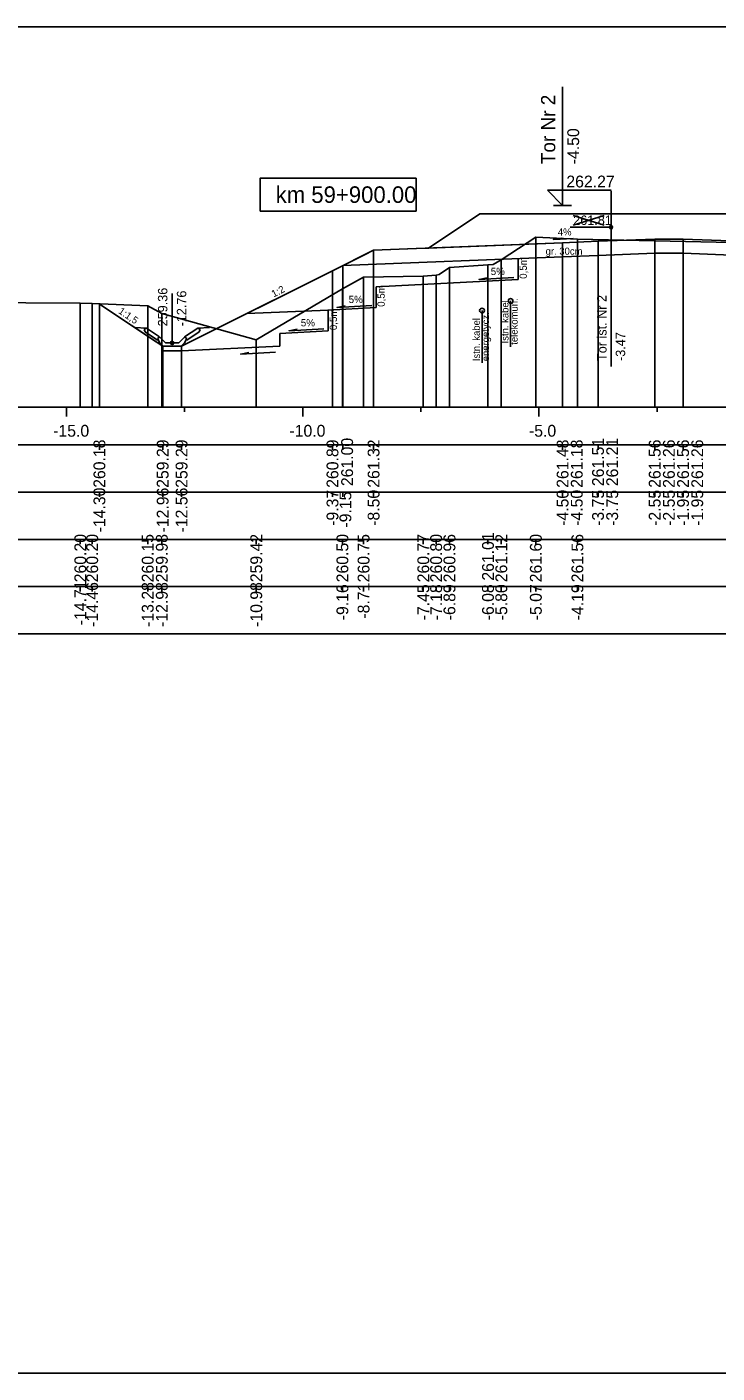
# Model space of a CAD drawing. Extents: x 6516023 to 6560129, y 5513077 to 5529206.
# Drawn here: x 6517839.38 to 6517853.98, y 5514451.16 to 5514479.66 of the extents above; entities that cross this region are included whole.
import ezdxf

# ---------------------------------------------------------------- set-up
doc = ezdxf.new("R2010")
doc.units = 0
for name, color, linetype in [('IR_default', 7, 'Continuous'), ('TOR_PRZEK_P-kable', 7, 'Continuous'), ('TOR_PRZEK_P-komponent', 7, 'Continuous'), ('TOR_PRZEK_P-odwodnienie', 7, 'Continuous'), ('TOR_PRZEK_P-opisy', 7, 'Continuous'), ('TOR_PRZEK_P-schodkowanie+wymiana', 7, 'Continuous'), ('TOR_PRZEK_P-tabelka istniejace', 7, 'Continuous'), ('TOR_PRZEK_P-tabelka projektowane', 7, 'Continuous'), ('TOR_PRZEK_P-teren istniejacy', 7, 'Continuous'), ('TOR_PRZEK_P-tory istniejace', 7, 'Continuous'), ('TOR_PRZEK_P-tory projektowane', 7, 'Continuous'), ('TOR_PRZEK_P-uklad odniesienia', 7, 'Continuous'), ('TOR_PRZEK_P-warstwa ochronna I', 7, 'Continuous'), ('TOR_PRZEK_P-warstwa ochronna II', 7, 'Continuous'), ('TOR_PS_T-skarpy projektowane', 7, 'Continuous'), ('TOR_RAMKI-ramka+tabelka 1', 7, 'Continuous')]:
    doc.layers.add(name, color=color, linetype=linetype)

msp = doc.modelspace()

# ---------------------------------------------------------------- linework, layer by layer
at = {"layer": 'IR_default'}
msp.add_lwpolyline([(6517840.91, 5514473.789), (6517841.969, 5514473.083), (6517842.249, 5514472.896), (6517842.339, 5514472.896), (6517842.649, 5514472.896), (6517843.365, 5514473.254), (6517845.843, 5514474.493), (6517845.843, 5514474.493), (6517845.843, 5514474.493), (6517846.518, 5514474.831), (6517846.713, 5514474.928), (6517847.617, 5514474.964), (6517847.878, 5514474.975), (6517848.72, 5514475.536), (6517848.963, 5514475.698), (6517851.679, 5514475.698), (6517852.463, 5514475.698), (6517853.239, 5514475.698), (6517853.463, 5514475.698), (6517856.179, 5514475.698)], dxfattribs=at)
at = {"layer": 'TOR_PRZEK_P-kable'}
for p, q in [((6517849.613, 5514473.854), (6517849.613, 5514472.88)), ((6517849.008, 5514473.651), (6517849.008, 5514472.542))]:
    msp.add_line(p, q, dxfattribs=at)
for centre in [(6517849.613, 5514473.854), (6517849.008, 5514473.651)]:
    msp.add_circle(centre, 0.05, dxfattribs=at)
at = {"layer": 'TOR_PRZEK_P-komponent'}
msp.add_lwpolyline([(6517848.963, 5514475.698), (6517852.463, 5514475.698), (6517853.463, 5514475.698), (6517856.963, 5514475.698), (6517857.513, 5514475.699), (6517861.013, 5514475.699), (6517862.358, 5514474.802), (6517858.513, 5514474.956), (6517855.213, 5514475.088), (6517854.463, 5514475.118), (6517853.263, 5514475.166), (6517852.663, 5514475.166), (6517851.463, 5514475.118), (6517850.713, 5514475.088), (6517847.878, 5514474.975)], close=True, dxfattribs=at)
at = {"layer": 'TOR_PRZEK_P-odwodnienie'}
for p, q in [((6517842.449, 5514472.966), (6517842.449, 5514474.01)), ((6517842.185, 5514473.092), (6517841.904, 5514473.279)), ((6517842.714, 5514473.092), (6517842.994, 5514473.279)), ((6517842.14, 5514473.025), (6517841.879, 5514473.2)), ((6517842.151, 5514473.042), (6517842.14, 5514473.025)), ((6517842.142, 5514473.061), (6517842.189, 5514473.085)), ((6517842.185, 5514473.092), (6517842.176, 5514473.079)), ((6517842.309, 5514472.966), (6517842.189, 5514473.085)), ((6517842.589, 5514472.966), (6517842.709, 5514473.085)), ((6517842.709, 5514473.085), (6517842.757, 5514473.061)), ((6517842.714, 5514473.092), (6517842.722, 5514473.079)), ((6517842.747, 5514473.042), (6517842.758, 5514473.025)), ((6517842.758, 5514473.025), (6517843.02, 5514473.2)), ((6517842.259, 5514472.896), (6517842.639, 5514472.896)), ((6517842.309, 5514472.966), (6517842.589, 5514472.966))]:
    msp.add_line(p, q, dxfattribs=at)
for points in [[(6517841.658, 5514473.291), (6517841.904, 5514473.279)], [(6517841.854, 5514473.252), (6517841.904, 5514473.279)], [(6517843.241, 5514473.291), (6517842.994, 5514473.279)], [(6517843.044, 5514473.252), (6517842.994, 5514473.279)], [(6517841.854, 5514473.252), (6517841.879, 5514473.2)], [(6517842.176, 5514473.079), (6517842.141, 5514473.061)], [(6517842.141, 5514473.061), (6517842.151, 5514473.042)], [(6517842.189, 5514472.966), (6517842.142, 5514473.061)], [(6517842.709, 5514472.966), (6517842.757, 5514473.061)], [(6517842.722, 5514473.079), (6517842.757, 5514473.061)], [(6517842.757, 5514473.061), (6517842.747, 5514473.042)], [(6517843.044, 5514473.252), (6517843.02, 5514473.2)], [(6517842.259, 5514472.896), (6517842.189, 5514472.966)], [(6517842.249, 5514472.896), (6517842.248, 5514472.897), (6517842.249, 5514472.896), (6517842.248, 5514472.896), (6517842.249, 5514472.896), (6517842.249, 5514472.896), (6517842.249, 5514472.896), (6517842.249, 5514472.897)], [(6517842.249, 5514472.896), (6517842.249, 5514472.896), (6517842.249, 5514472.896), (6517842.249, 5514472.895), (6517842.249, 5514472.896), (6517842.25, 5514472.895), (6517842.249, 5514472.896), (6517842.25, 5514472.896)], [(6517842.649, 5514472.896), (6517842.249, 5514472.896), (6517842.249, 5514472.796), (6517842.649, 5514472.796), (6517842.649, 5514472.896)], [(6517842.639, 5514472.896), (6517842.709, 5514472.966)], [(6517842.649, 5514472.896), (6517842.648, 5514472.897), (6517842.649, 5514472.896), (6517842.648, 5514472.896), (6517842.649, 5514472.896), (6517842.649, 5514472.896), (6517842.649, 5514472.896), (6517842.649, 5514472.897)], [(6517842.649, 5514472.896), (6517842.649, 5514472.896), (6517842.649, 5514472.896), (6517842.649, 5514472.895), (6517842.649, 5514472.896), (6517842.65, 5514472.895), (6517842.649, 5514472.896), (6517842.65, 5514472.896)]]:
    msp.add_lwpolyline(points, dxfattribs=at)
msp.add_circle((6517842.449, 5514472.966), 0.035, dxfattribs=at)
at = {"layer": 'TOR_PRZEK_P-opisy'}
msp.add_lwpolyline([(6517850.936, 5514475.175), (6517850.518, 5514475.156), (6517850.686, 5514475.184)], dxfattribs=at)
at = {"layer": 'TOR_PRZEK_P-schodkowanie+wymiana'}
for p, q in [((6517849.775, 5514474.751), (6517849.775, 5514474.307)), ((6517849.775, 5514474.307), (6517846.767, 5514474.157)), ((6517846.767, 5514474.157), (6517846.767, 5514473.714)), ((6517845.755, 5514473.663), (6517844.033, 5514473.588)), ((6517846.767, 5514473.714), (6517845.744, 5514473.663)), ((6517845.755, 5514473.663), (6517845.755, 5514473.22)), ((6517845.755, 5514473.22), (6517844.732, 5514473.169)), ((6517844.732, 5514473.169), (6517844.732, 5514472.9)), ((6517844.732, 5514472.9), (6517842.649, 5514472.796))]:
    msp.add_line(p, q, dxfattribs=at)
at = {"layer": 'TOR_PRZEK_P-tabelka istniejace'}
for p, q in [((6517840.506, 5514468.706), (6517840.506, 5514468.806)), ((6517840.757, 5514468.706), (6517840.757, 5514468.806)), ((6517841.932, 5514468.706), (6517841.932, 5514468.806)), ((6517842.231, 5514468.706), (6517842.231, 5514468.806)), ((6517844.23, 5514468.706), (6517844.23, 5514468.806)), ((6517846.053, 5514468.706), (6517846.053, 5514468.806)), ((6517846.501, 5514468.706), (6517846.501, 5514468.806)), ((6517847.765, 5514468.706), (6517847.765, 5514468.806)), ((6517848.037, 5514468.706), (6517848.037, 5514468.806)), ((6517848.319, 5514468.706), (6517848.319, 5514468.806)), ((6517849.134, 5514468.706), (6517849.134, 5514468.806)), ((6517849.416, 5514468.706), (6517849.416, 5514468.806)), ((6517850.147, 5514468.706), (6517850.147, 5514468.806)), ((6517851.027, 5514468.706), (6517851.027, 5514468.806)), ((6517814.163, 5514467.806), (6517897.963, 5514467.806)), ((6517840.506, 5514467.706), (6517840.506, 5514467.806)), ((6517840.757, 5514467.706), (6517840.757, 5514467.806)), ((6517841.932, 5514467.706), (6517841.932, 5514467.806)), ((6517842.231, 5514467.706), (6517842.231, 5514467.806)), ((6517844.23, 5514467.706), (6517844.23, 5514467.806)), ((6517846.053, 5514467.706), (6517846.053, 5514467.806)), ((6517846.501, 5514467.706), (6517846.501, 5514467.806)), ((6517847.765, 5514467.706), (6517847.765, 5514467.806)), ((6517848.037, 5514467.706), (6517848.037, 5514467.806)), ((6517848.319, 5514467.706), (6517848.319, 5514467.806)), ((6517849.134, 5514467.706), (6517849.134, 5514467.806)), ((6517849.416, 5514467.706), (6517849.416, 5514467.806)), ((6517850.147, 5514467.706), (6517850.147, 5514467.806)), ((6517851.027, 5514467.706), (6517851.027, 5514467.806))]:
    msp.add_line(p, q, dxfattribs=at)
for points in [[(6517850.147, 5514475.204), (6517850.147, 5514471.806), (6517850.147, 5514471.676), (6517850.147, 5514471.606)], [(6517851.027, 5514475.162), (6517851.027, 5514471.806), (6517851.027, 5514471.676), (6517851.027, 5514471.606)], [(6517849.416, 5514474.725), (6517849.416, 5514471.806), (6517849.416, 5514471.676), (6517849.416, 5514471.606)], [(6517848.319, 5514474.561), (6517848.319, 5514471.806), (6517848.319, 5514471.676), (6517848.319, 5514471.606)], [(6517849.134, 5514474.616), (6517849.134, 5514471.806), (6517849.134, 5514471.676), (6517849.134, 5514471.606)], [(6517846.501, 5514474.355), (6517846.501, 5514471.806), (6517846.501, 5514471.676), (6517846.501, 5514471.606)], [(6517847.765, 5514474.378), (6517847.765, 5514471.806), (6517847.765, 5514471.676), (6517847.765, 5514471.606)], [(6517848.037, 5514474.402), (6517848.037, 5514471.806), (6517848.037, 5514471.676), (6517848.037, 5514471.606)], [(6517846.053, 5514474.11), (6517846.053, 5514471.806), (6517846.053, 5514471.676), (6517846.053, 5514471.606)], [(6517840.506, 5514473.811), (6517840.506, 5514471.806), (6517840.506, 5514471.676), (6517840.506, 5514471.606)], [(6517840.757, 5514473.803), (6517840.757, 5514471.806), (6517840.757, 5514471.676), (6517840.757, 5514471.606)], [(6517841.932, 5514473.751), (6517841.932, 5514471.806), (6517841.932, 5514471.676), (6517841.932, 5514471.606)], [(6517842.231, 5514473.59), (6517842.231, 5514471.806), (6517842.231, 5514471.676), (6517842.231, 5514471.606)], [(6517844.23, 5514473.028), (6517844.23, 5514471.806), (6517844.23, 5514471.676), (6517844.23, 5514471.606)]]:
    msp.add_lwpolyline(points, dxfattribs=at)
msp.add_lwpolyline([(6517814.163, 5514468.806), (6517814.163, 5514466.806), (6517897.963, 5514466.806), (6517897.963, 5514468.806)], close=True, dxfattribs=at)
at = {"layer": 'TOR_PRZEK_P-tabelka projektowane'}
for p, q in [((6517840.91, 5514470.706), (6517840.91, 5514470.806)), ((6517842.249, 5514470.706), (6517842.249, 5514470.806)), ((6517842.649, 5514470.706), (6517842.649, 5514470.806)), ((6517845.843, 5514470.706), (6517845.843, 5514470.806)), ((6517846.061, 5514470.706), (6517846.061, 5514470.806)), ((6517846.713, 5514470.706), (6517846.713, 5514470.806)), ((6517850.713, 5514470.706), (6517850.713, 5514470.806)), ((6517850.713, 5514470.706), (6517850.713, 5514470.806)), ((6517851.463, 5514470.706), (6517851.463, 5514470.806)), ((6517851.463, 5514470.706), (6517851.463, 5514470.806)), ((6517852.663, 5514470.706), (6517852.663, 5514470.806)), ((6517852.663, 5514470.706), (6517852.663, 5514470.806)), ((6517853.263, 5514470.706), (6517853.263, 5514470.806)), ((6517853.263, 5514470.706), (6517853.263, 5514470.806)), ((6517814.163, 5514469.806), (6517897.963, 5514469.806)), ((6517840.91, 5514469.706), (6517840.91, 5514469.806)), ((6517842.249, 5514469.706), (6517842.249, 5514469.806)), ((6517842.649, 5514469.706), (6517842.649, 5514469.806)), ((6517845.843, 5514469.706), (6517845.843, 5514469.806)), ((6517846.061, 5514469.706), (6517846.061, 5514469.806)), ((6517846.713, 5514469.706), (6517846.713, 5514469.806)), ((6517850.713, 5514469.706), (6517850.713, 5514469.806)), ((6517850.713, 5514469.706), (6517850.713, 5514469.806)), ((6517851.463, 5514469.706), (6517851.463, 5514469.806)), ((6517851.463, 5514469.706), (6517851.463, 5514469.806)), ((6517852.663, 5514469.706), (6517852.663, 5514469.806)), ((6517852.663, 5514469.706), (6517852.663, 5514469.806)), ((6517853.263, 5514469.706), (6517853.263, 5514469.806)), ((6517853.263, 5514469.706), (6517853.263, 5514469.806))]:
    msp.add_line(p, q, dxfattribs=at)
for points in [[(6517850.713, 5514475.088), (6517850.713, 5514471.806), (6517850.713, 5514471.676), (6517850.713, 5514471.606)], [(6517851.463, 5514475.118), (6517851.463, 5514471.806), (6517851.463, 5514471.676), (6517851.463, 5514471.606)], [(6517852.663, 5514475.166), (6517852.663, 5514471.806), (6517852.663, 5514471.676), (6517852.663, 5514471.606)], [(6517853.263, 5514475.166), (6517853.263, 5514471.806), (6517853.263, 5514471.676), (6517853.263, 5514471.606)], [(6517846.713, 5514474.928), (6517846.713, 5514471.806), (6517846.713, 5514471.676), (6517846.713, 5514471.606)], [(6517850.713, 5514474.788), (6517850.713, 5514471.806), (6517850.713, 5514471.676), (6517850.713, 5514471.606)], [(6517851.463, 5514474.818), (6517851.463, 5514471.806), (6517851.463, 5514471.676), (6517851.463, 5514471.606)], [(6517852.663, 5514474.866), (6517852.663, 5514471.806), (6517852.663, 5514471.676), (6517852.663, 5514471.606)], [(6517853.263, 5514474.866), (6517853.263, 5514471.806), (6517853.263, 5514471.676), (6517853.263, 5514471.606)], [(6517845.843, 5514474.493), (6517845.843, 5514471.806), (6517845.843, 5514471.676), (6517845.843, 5514471.606)], [(6517846.061, 5514474.602), (6517846.061, 5514471.806), (6517846.061, 5514471.676), (6517846.061, 5514471.606)], [(6517840.91, 5514473.789), (6517840.91, 5514471.806), (6517840.91, 5514471.676), (6517840.91, 5514471.606)], [(6517842.249, 5514472.896), (6517842.249, 5514471.806), (6517842.249, 5514471.676), (6517842.249, 5514471.606)], [(6517842.649, 5514472.896), (6517842.649, 5514471.806), (6517842.649, 5514471.676), (6517842.649, 5514471.606)]]:
    msp.add_lwpolyline(points, dxfattribs=at)
msp.add_lwpolyline([(6517814.163, 5514470.806), (6517814.163, 5514468.806), (6517897.963, 5514468.806), (6517897.963, 5514470.806)], close=True, dxfattribs=at)
at = {"layer": 'TOR_PRZEK_P-teren istniejacy'}
msp.add_lwpolyline([(6517837.044, 5514473.827), (6517840.506, 5514473.811), (6517840.757, 5514473.803), (6517841.932, 5514473.751), (6517842.231, 5514473.59), (6517844.23, 5514473.028), (6517846.053, 5514474.11), (6517846.501, 5514474.355), (6517847.765, 5514474.378), (6517848.037, 5514474.402), (6517848.103, 5514474.417), (6517848.319, 5514474.561), (6517849.134, 5514474.616), (6517849.246, 5514474.627), (6517849.416, 5514474.725), (6517850.147, 5514475.204), (6517851.027, 5514475.162), (6517859.84, 5514474.971)], dxfattribs=at)
at = {"layer": 'TOR_PRZEK_P-tory istniejace'}
for p, q in [((6517851.738, 5514476.189), (6517851.738, 5514472.469)), ((6517850.938, 5514475.461), (6517851.59, 5514475.664)), ((6517850.938, 5514475.664), (6517851.59, 5514475.461)), ((6517851.738, 5514475.414), (6517850.872, 5514475.414))]:
    msp.add_line(p, q, dxfattribs=at)
msp.add_circle((6517851.738, 5514475.414), 0.035, dxfattribs=at)
at = {"layer": 'TOR_PRZEK_P-tory projektowane'}
for p, q in [((6517850.713, 5514476.756), (6517850.713, 5514478.388)), ((6517850.713, 5514476.756), (6517850.713, 5514475.878)), ((6517850.713, 5514475.878), (6517850.394, 5514476.197)), ((6517850.394, 5514476.197), (6517851.738, 5514476.197)), ((6517850.521, 5514475.878), (6517850.905, 5514475.878))]:
    msp.add_line(p, q, dxfattribs=at)
at = {"layer": 'TOR_PRZEK_P-uklad odniesienia'}
for p, q in [((6517817.963, 5514471.606), (6517897.963, 5514471.606)), ((6517840.213, 5514471.406), (6517840.213, 5514471.606)), ((6517842.713, 5514471.506), (6517842.713, 5514471.606)), ((6517845.213, 5514471.406), (6517845.213, 5514471.606)), ((6517847.713, 5514471.506), (6517847.713, 5514471.606)), ((6517850.213, 5514471.406), (6517850.213, 5514471.606)), ((6517852.713, 5514471.506), (6517852.713, 5514471.606))]:
    msp.add_line(p, q, dxfattribs=at)
msp.add_lwpolyline([(6517847.613, 5514476.456), (6517844.313, 5514476.456), (6517844.313, 5514475.756), (6517847.613, 5514475.756)], close=True, dxfattribs=at)
at = {"layer": 'TOR_PRZEK_P-warstwa ochronna I'}
msp.add_lwpolyline([(6517846.061, 5514474.602), (6517850.713, 5514474.788), (6517851.463, 5514474.818), (6517852.663, 5514474.866), (6517853.263, 5514474.866), (6517854.463, 5514474.818), (6517855.213, 5514474.788), (6517858.513, 5514474.656), (6517859.263, 5514474.626), (6517864.215, 5514474.428)], dxfattribs=at)
at = {"layer": 'TOR_PRZEK_P-warstwa ochronna II'}
msp.add_lwpolyline([(6517840.91, 5514473.789), (6517842.249, 5514472.896), (6517842.649, 5514472.896), (6517845.843, 5514474.493), (6517845.843, 5514474.493), (6517846.713, 5514474.928), (6517850.713, 5514475.088), (6517851.463, 5514475.118), (6517852.663, 5514475.166), (6517853.263, 5514475.166), (6517854.463, 5514475.118), (6517855.213, 5514475.088), (6517858.513, 5514474.956), (6517859.263, 5514474.926), (6517863.563, 5514474.754), (6517864.432, 5514474.319), (6517866.686, 5514473.192), (6517867.086, 5514473.192), (6517868.241, 5514473.962)], dxfattribs=at)
at = {"layer": 'TOR_PS_T-skarpy projektowane'}
for points in [[(6517849.682, 5514474.352), (6517848.946, 5514474.312), (6517849.119, 5514474.343)], [(6517846.674, 5514473.759), (6517845.939, 5514473.719), (6517846.111, 5514473.75)], [(6517845.661, 5514473.265), (6517844.926, 5514473.225), (6517845.099, 5514473.256)], [(6517844.639, 5514472.771), (6517843.903, 5514472.731), (6517844.076, 5514472.762)]]:
    msp.add_lwpolyline(points, dxfattribs=at)
at = {"layer": 'TOR_RAMKI-ramka+tabelka 1'}
msp.add_lwpolyline([(6517724.513, 5514479.656), (6517972.013, 5514479.656), (6517972.013, 5514451.156), (6517724.513, 5514451.156)], close=True, dxfattribs=at)

# ---------------------------------------------------------------- texts
at = {"layer": 'TOR_PRZEK_P-kable'}
for s, height, p in [('Istn. kabel', 0.14999, (6517849.568, 5514472.956)), ('telekomun.', 0.15, (6517849.762, 5514472.928)), ('energetycz.', 0.14999, (6517849.157, 5514472.578)), ('Istn. kabel', 0.14999, (6517848.963, 5514472.578))]:
    msp.add_text(s, height=height, rotation=90.0511, dxfattribs=at).set_placement(p)
at = {"layer": 'TOR_PRZEK_P-odwodnienie'}
for s, p in [('259.36', (6517842.349, 5514473.316)), ('-12.76', (6517842.749, 5514473.316))]:
    msp.add_text(s, height=0.2, rotation=90, dxfattribs=at).set_placement(p)
at = {"layer": 'TOR_PRZEK_P-opisy'}
for s, rotation, p in [('4%', 0.1515, (6517850.613, 5514475.24)), ('1:2', 27.0864, (6517844.599, 5514473.927)), ('1:1,5', 325.9299, (6517841.298, 5514473.606))]:
    msp.add_text(s, height=0.15, rotation=rotation, dxfattribs=at).set_placement(p)
at = {"layer": 'TOR_PRZEK_P-schodkowanie+wymiana'}
for p in [(6517849.957, 5514474.323), (6517846.949, 5514473.73), (6517845.937, 5514473.236)]:
    msp.add_text('0,5m', height=0.1545, rotation=90, dxfattribs=at).set_placement(p)
at = {"layer": 'TOR_PRZEK_P-tabelka istniejace'}
for s, p in [('260.20', (6517840.631, 5514467.898)), ('260.20', (6517840.882, 5514467.898)), ('260.15', (6517842.057, 5514467.897)), ('259.98', (6517842.356, 5514467.898)), ('259.42', (6517844.355, 5514467.9)), ('260.50', (6517846.178, 5514467.898)), ('260.75', (6517846.626, 5514467.897)), ('260.77', (6517847.89, 5514467.898)), ('260.80', (6517848.162, 5514467.898)), ('260.96', (6517848.444, 5514467.898)), ('261.01', (6517849.259, 5514467.933)), ('261.12', (6517849.541, 5514467.9)), ('261.60', (6517850.272, 5514467.898)), ('261.56', (6517851.152, 5514467.898)), ('-14.71', (6517840.631, 5514466.989)), ('-14.46', (6517840.882, 5514466.954)), ('-13.28', (6517842.057, 5514466.954)), ('-12.98', (6517842.356, 5514466.954)), ('-10.98', (6517844.355, 5514466.954)), ('-8.71', (6517846.626, 5514467.129)), ('-9.16', (6517846.178, 5514467.094)), ('-7.45', (6517847.89, 5514467.093)), ('-7.18', (6517848.162, 5514467.094)), ('-6.89', (6517848.444, 5514467.094)), ('-6.08', (6517849.259, 5514467.094)), ('-5.80', (6517849.541, 5514467.094)), ('-5.07', (6517850.272, 5514467.094)), ('-4.19', (6517851.152, 5514467.094))]:
    msp.add_text(s, height=0.25, rotation=90, dxfattribs=at).set_placement(p)
at = {"layer": 'TOR_PRZEK_P-tabelka projektowane'}
for s, p in [('260.18', (6517841.035, 5514469.898)), ('259.29', (6517842.374, 5514469.898)), ('259.29', (6517842.774, 5514469.898)), ('260.89', (6517845.968, 5514469.898)), ('261.00', (6517846.278, 5514469.934)), ('261.32', (6517846.838, 5514469.9)), ('261.48', (6517850.838, 5514469.898)), ('261.18', (6517851.138, 5514469.898)), ('261.51', (6517851.588, 5514469.933)), ('261.21', (6517851.888, 5514469.933)), ('261.56', (6517852.788, 5514469.898)), ('261.26', (6517853.088, 5514469.898)), ('261.56', (6517853.388, 5514469.898)), ('261.26', (6517853.688, 5514469.898)), ('-14.30', (6517841.035, 5514468.955)), ('-12.96', (6517842.374, 5514468.954)), ('-12.56', (6517842.774, 5514468.954)), ('-9.37', (6517845.968, 5514469.094)), ('-9.15', (6517846.242, 5514469.057)), ('-8.50', (6517846.838, 5514469.094)), ('-4.50', (6517850.838, 5514469.094)), ('-4.50', (6517851.138, 5514469.094)), ('-3.75', (6517851.588, 5514469.093)), ('-3.75', (6517851.888, 5514469.093)), ('-2.55', (6517852.788, 5514469.093)), ('-2.55', (6517853.088, 5514469.093)), ('-1.95', (6517853.388, 5514469.093)), ('-1.95', (6517853.688, 5514469.093))]:
    msp.add_text(s, height=0.25, rotation=90, dxfattribs=at).set_placement(p)
at = {"layer": 'TOR_PRZEK_P-tory istniejace'}
msp.add_text('261.81', height=0.2, dxfattribs=at).set_placement((6517850.938, 5514475.464))
for s, rotation, p in [('Tor ist. Nr 2', 90.0511, (6517851.644, 5514472.584)), ('-3.47', 90, (6517852.038, 5514472.584))]:
    msp.add_text(s, height=0.2, rotation=rotation, dxfattribs=at).set_placement(p)
at = {"layer": 'TOR_PRZEK_P-tory projektowane'}
for s, height, p in [('Tor Nr 2', 0.3, (6517850.558, 5514476.75)), ('-4.50', 0.25, (6517851.063, 5514476.748))]:
    msp.add_text(s, height=height, rotation=90, dxfattribs=at).set_placement(p)
msp.add_text('262.27', height=0.25, dxfattribs=at).set_placement((6517850.793, 5514476.258))
at = {"layer": 'TOR_PRZEK_P-uklad odniesienia'}
for s, height, p in [('km 59+900.00', 0.35, (6517844.641, 5514475.931)), ('-15.0', 0.25, (6517839.932, 5514470.981)), ('-10.0', 0.25, (6517844.932, 5514470.981)), ('-5.0', 0.25, (6517850.002, 5514470.981))]:
    msp.add_text(s, height=height, dxfattribs=at).set_placement(p)
at = {"layer": 'TOR_PRZEK_P-warstwa ochronna I'}
msp.add_text('gr. 30cm', height=0.15, dxfattribs=at).set_placement((6517850.354, 5514474.834))
at = {"layer": 'TOR_PS_T-skarpy projektowane'}
for p in [(6517849.193, 5514474.403), (6517846.186, 5514473.81), (6517845.173, 5514473.316)]:
    msp.add_text('5%', height=0.1545, dxfattribs=at).set_placement(p)

doc.saveas('drawing.dxf')
